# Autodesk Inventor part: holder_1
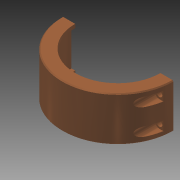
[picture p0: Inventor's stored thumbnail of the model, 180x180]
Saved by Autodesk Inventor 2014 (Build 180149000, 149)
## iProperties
Shininess: 64.0
Length Units: 11269
Angle Units: 11279
Time Units: 11290
Mass Units: 11283
Length Display Precision: 3
Angle Display Precision: 2
Created: 2002-09
Part Number: holder_1
Document SubType Name: Modeling
Designer: ales
Density: 1 g/cm^3
Material: Generic
Appearance: Copper
Density: 0.0
Volumn: 0.0
Area: 0.0
PropertySet Name: Model Information
Control State: 0
Master: False
Checked Out: False
Author: PaulN
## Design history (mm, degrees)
sketch "Sketch1"
  geometry: L1 (12.779, 19.85)-(12.779, -19.85) reference; L2 (12.779, -19.85)-(16.779, -19.85) reference; L3 (16.779, -19.85)-(16.779, -23.85) reference; L4 (16.779, -23.85)-(2.779, -23.85) reference; L5 (16.779, 23.85)-(16.779, 19.85) reference; L6 (2.779, 23.85)-(16.779, 23.85) reference; L7 (2.779, -23.85)-(2.779, 23.85); L8 (108.779, -19.85)-(16.779, -19.85) reference; L9 (62.779, -19.85)-(62.779, 12.267); L10 (16.779, 19.85)-(12.779, 19.85) reference
  constraints: 4 end point, 2 perpendicular, 1 midpoint, 1 parallel
revolve "Revolution1" sketch "Sketch1" stored, may be unused: angle "d0" = 180 deg
sketch "Sketch2"
  geometry: L1 (14, 0)-(0, 0) reference; L2 (14, 47.7)-(14, 0) reference; L3 (0, 47.7)-(14, 47.7) reference; L4 (0, 47.7)-(-92, 47.7) reference; L5 (-46, 47.7)-(-46, 10.278); L6 (9, 32.7)-(14, 32.7); L7 (9, 42.7)-(14, 42.7); L8 (9, 15)-(14, 15); L9 (9, 5)-(14, 5); L10 (-101, 32.7)-(-106, 32.7); L11 (-101, 42.7)-(-106, 42.7); L12 (-101, 15)-(-106, 15); L13 (-101, 5)-(-106, 5); L14 (-106, 32.7)-(-106, 42.7); L15 (-106, 15)-(-106, 5); C1 r 3 at (9, 37.7); C2 r 3 at (9, 10); C3 r 3 at (-101, 37.7); C4 r 3 at (-101, 10); A1 r 5 centre (9, 10) between (9, 15) and (9, 5); A2 r 5 centre (9, 37.7) between (9, 42.7) and (9, 32.7); A3 r 5 centre (-101, 37.7) between (-101, 32.7) and (-101, 42.7); A4 r 5 centre (-101, 10) between (-101, 5) and (-101, 15)
  constraints: 22 end point, 12 symmetric about line, 8 centre point, 8 point on circle, 5 perpendicular, 4 coincident, 4 point on line, 4 tangent, 2 equal length, 2 equal radius, 1 midpoint, 1 vertical alignment, 8 other
  dimensions: "d1" = 10 diameter of A2; "d2" = 5 distance from line of L2 A2.centre; "d3" = 6 diameter of C1; "d4" = 10 distance from line of L3 A2.centre; "d5" = 10 distance from line of L1 A1.centre
extrude "Extrusion1" cut sketch "Sketch2" stored distance "d6" = 10; taper "d7" = 0 deg
workplane "Work Plane1"
workplane "Work Plane2"
extrude "Extrusion2" cut sketch "Sketch2" stored distance "d9" = 10; taper "d10" = 0 deg
chamfer "Chamfer1" distance "d11" = 1; stored, may be unused: second distance "d12" = 1, angle "d13" = 45 deg
body "Solid1"
node "Reference2"
node "Reference3"
node "Reference4"
node "Reference5"
node "Reference6"
node "Reference7"
node "Reference8"
node "Reference9"
